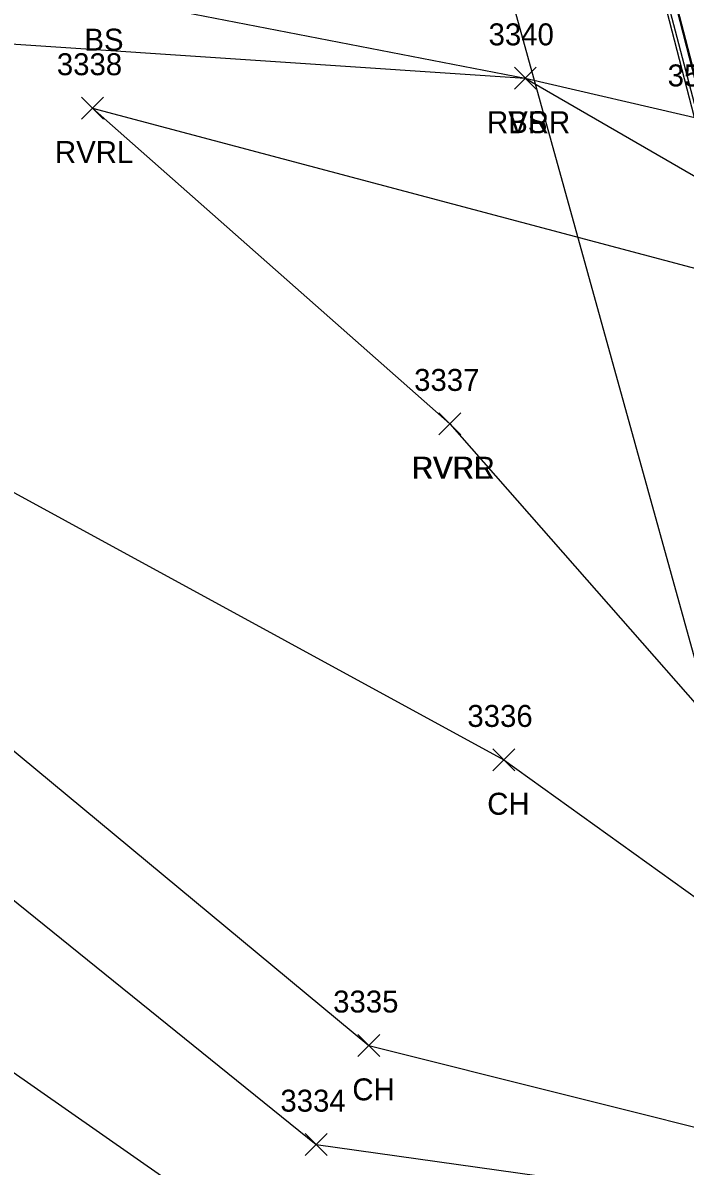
# Model space of a CAD drawing. Extents: x 1601151 to 1602912, y 499508 to 501770.
# Drawn here: x 1601482.2 to 1601542.5, y 500689.8 to 500794 of the extents above; entities that cross this region are included whole.
import ezdxf

# ---------------------------------------------------------------- set-up
doc = ezdxf.new("R2010")
doc.units = 0
for name, color, linetype in [('BDC', 7, 'Continuous'), ('BF', 7, 'Continuous'), ('BR', 7, 'Continuous'), ('L_A', 7, 'Continuous'), ('L_I', 7, 'Continuous'), ('L_TIC', 7, 'Continuous'), ('LAWE', 7, 'Continuous'), ('LDEFAULT', 7, 'Continuous'), ('LELB', 7, 'Continuous'), ('UCO', 7, 'Continuous')]:
    doc.layers.add(name, color=color, linetype=linetype)

msp = doc.modelspace()

# ---------------------------------------------------------------- linework, layer by layer
at = {"layer": 'BDC'}
for points in [[(1601521.71, 500869.96), (1601522.4, 500870.19), (1601530.67, 500838.29), (1601539.74, 500803.09), (1601549.8, 500763.94), (1601562.9, 500713.2), (1601575.3, 500665.09), (1601584.68, 500628.8), (1601595.24, 500588.1), (1601603.29, 500556.62), (1601602.83, 500556.33)], [(1601522.54, 500870.25), (1601530.89, 500838.16), (1601539.77, 500803.18), (1601550.06, 500763.65), (1601563.09, 500713.39), (1601575.5, 500665.1), (1601584.83, 500628.83), (1601595.28, 500588.33), (1601603.43, 500556.59), (1601602.76, 500556.07)]]:
    msp.add_lwpolyline(points, dxfattribs=at)
at = {"layer": 'BF'}
msp.add_lwpolyline([(1601521.71, 500869.96), (1601529.93, 500837.54), (1601538.82, 500802.89), (1601549.01, 500763.54), (1601561.99, 500712.94), (1601574.42, 500664.92), (1601583.83, 500628.56), (1601594.34, 500587.94), (1601602.83, 500556.33)], dxfattribs=at)
at = {"layer": 'BR'}
msp.add_lwpolyline([(1601521.92, 500869.37), (1601530.02, 500838.06), (1601539.08, 500802.86), (1601549.33, 500763.87), (1601562.42, 500713.04), (1601574.56, 500665.15), (1601584.1, 500628.64), (1601594.6, 500587.84), (1601602.42, 500557.54)], dxfattribs=at)
at = {"layer": 'L_TIC'}
for points in [[(1601526.96, 500787.91), (1601528.96, 500789.91)], [(1601528.96, 500787.91), (1601526.96, 500789.91)], [(1601526.96, 500787.91), (1601528.96, 500789.91)], [(1601528.96, 500787.91), (1601526.96, 500789.91)], [(1601487.53, 500785.19), (1601489.53, 500787.19)], [(1601489.53, 500785.19), (1601487.53, 500787.19)], [(1601520.09, 500756.43), (1601522.09, 500758.43)], [(1601522.09, 500756.43), (1601520.09, 500758.43)], [(1601520.09, 500756.43), (1601522.09, 500758.43)], [(1601522.09, 500756.43), (1601520.09, 500758.43)], [(1601525, 500725.82), (1601527, 500727.82)], [(1601527, 500725.82), (1601525, 500727.82)], [(1601512.71, 500699.8), (1601514.71, 500701.8)], [(1601514.71, 500699.8), (1601512.71, 500701.8)], [(1601507.9, 500690.77), (1601509.9, 500692.77)], [(1601509.9, 500690.77), (1601507.9, 500692.77)]]:
    msp.add_lwpolyline(points, dxfattribs=at)
at = {"layer": 'LAWE'}
for points in [[(1601318.62, 500789.62), (1601362.93, 500806.22), (1601394.46, 500804.48), (1601434.19, 500795.17), (1601527.96, 500788.91), (1601546.38, 500778.25), (1601558, 500777.29), (1601574.08, 500771.8), (1601598.01, 500757.12), (1601667.95, 500738.14), (1601705.28, 500715.12), (1601735.85, 500687.88), (1601768.33, 500671.26), (1601783.77, 500659.22)], [(1601521.09, 500757.43), (1601488.53, 500786.19), (1601547.39, 500770.55), (1601549.08, 500761.62), (1601572.73, 500720.13), (1601584.11, 500723.14), (1601587.17, 500723.02)], [(1601521.09, 500757.43), (1601560.31, 500712.79), (1601565, 500710.16), (1601565.18, 500704.96), (1601578.99, 500700.46), (1601594.09, 500700.38), (1601635.3, 500697.93), (1601669.09, 500704.24), (1601677.01, 500717.93), (1601649.99, 500725.34), (1601626.36, 500742.54), (1601583.16, 500733.4), (1601587.17, 500723.02)]]:
    msp.add_lwpolyline(points, dxfattribs=at)
at = {"layer": 'LDEFAULT'}
for points in [[(1601337.45, 500787.94), (1601362.97, 500800.69), (1601393.84, 500792.74), (1601431.56, 500786.24), (1601466, 500759.52), (1601526, 500726.82), (1601566.27, 500697.9), (1601580.09, 500695.39), (1601593.87, 500695.15), (1601641.19, 500685.49), (1601672.03, 500699.21), (1601695.98, 500708.01), (1601703.42, 500706.03), (1601734.4, 500680.19), (1601767.36, 500664.87), (1601779.68, 500657.31)], [(1601339.09, 500785.52), (1601337.45, 500787.94), (1601364.5, 500789.17), (1601390.07, 500781.72), (1601419.33, 500750.23), (1601457.25, 500747.59), (1601513.71, 500700.8), (1601568.04, 500687.18), (1601598.22, 500676.18), (1601647.03, 500668.88), (1601695.93, 500672.79), (1601756.55, 500665.64), (1601778.58, 500654.09)], [(1601301.76, 500763.28), (1601339.09, 500785.52), (1601365.11, 500777.53), (1601390.18, 500773.26), (1601417.2, 500745.85), (1601452.03, 500737.65), (1601508.9, 500691.77), (1601569.64, 500683.25), (1601580.39, 500680.59), (1601586.29, 500672.56), (1601600.69, 500667.89), (1601646.7, 500657.93), (1601688.58, 500663.11)], [(1601303.68, 500759.4), (1601367.74, 500774.76), (1601385.3, 500764.32), (1601413.55, 500740.04), (1601448.35, 500721.35), (1601503.88, 500682.57), (1601578.22, 500651.86), (1601591.68, 500650.62), (1601603.79, 500656.64), (1601648.59, 500654.17), (1601682.93, 500659.64), (1601726.96, 500654.03), (1601736.69, 500654.19), (1601757.22, 500650.94), (1601774.12, 500647.76)]]:
    msp.add_lwpolyline(points, dxfattribs=at)
at = {"layer": 'LELB'}
msp.add_lwpolyline([(1601316.84, 500806.72), (1601362.81, 500808.47), (1601394.06, 500806.3), (1601436.22, 500803.55), (1601489.34, 500796.43), (1601527.96, 500788.91), (1601544.19, 500785.17)], dxfattribs=at)
at = {"layer": 'UCO'}
msp.add_lwpolyline([(1601595.97, 500546.62), (1601489.93, 500928.89)], dxfattribs=at)

# ---------------------------------------------------------------- texts
at = {"layer": 'L_A'}
for s, p in [('BS', (1601487.78, 500791.43)), ('RVRR', (1601524.47, 500783.91)), ('BS', (1601526.4, 500783.91)), ('RVRL', (1601485.1, 500781.19)), ('RVRR', (1601517.6, 500752.43)), ('RVRL', (1601517.66, 500752.43)), ('CH', (1601524.49, 500721.82)), ('CH', (1601512.2, 500695.8))]:
    msp.add_text(s, height=2, dxfattribs=at).set_placement(p)
at = {"layer": 'L_I'}
for s, p in [('3340', (1601524.61, 500791.91)), ('3340', (1601524.61, 500791.91)), ('3338', (1601485.27, 500789.19)), ('3524', (1601540.93, 500788.17)), ('3524', (1601540.93, 500788.17)), ('3337', (1601517.83, 500760.43)), ('3337', (1601517.83, 500760.43)), ('3336', (1601522.68, 500729.82)), ('3335', (1601510.45, 500703.8)), ('3334', (1601505.64, 500694.77))]:
    msp.add_text(s, height=2, dxfattribs=at).set_placement(p)

doc.saveas('drawing.dxf')
